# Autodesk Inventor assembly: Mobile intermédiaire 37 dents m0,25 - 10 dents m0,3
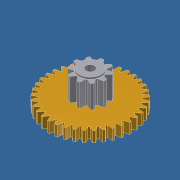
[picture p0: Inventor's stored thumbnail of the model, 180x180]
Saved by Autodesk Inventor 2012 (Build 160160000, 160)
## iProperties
Created: 2011-10
Part Number: Mobile intermédiaire 37 dents m0,25 - 10 dents m0,3
Document SubType Name: Assembly
Designer: Laur
Author: Laur
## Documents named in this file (3)
- D:\Formulaire\Sujet CIM 2012\Modélisation_7970_shimano\Mobile intermédiaire 37 dents m0,25 - 10 dents m0,3.iam
- D:\Formulaire\Sujet CIM 2012\Modélisation_7970_shimano\Pignon arbré creux 10 dents m0,3.ipt
- D:\Formulaire\Sujet CIM 2012\Modélisation_7970_shimano\Mobile intermédiaire 37 dents m0,25 - 10 dents m0,3\Design Accelerator\Engrenages cylindriques3.iam
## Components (2 placed, 2 different names)
1. Pignon arbré creux 10 dents m0,3:1 — Placage:1, Placage:2
2. Engrenages cylindriques:1 [sub-assembly] — Placage:1, Placage:2
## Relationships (2: Mate 2)
- Placage:1 [Mate]: Pignon arbré creux 10 dents m0,3:1 ↔ Engrenages cylindriques:1
- Placage:2 [Mate]: Pignon arbré creux 10 dents m0,3:1 ↔ Engrenages cylindriques:1
